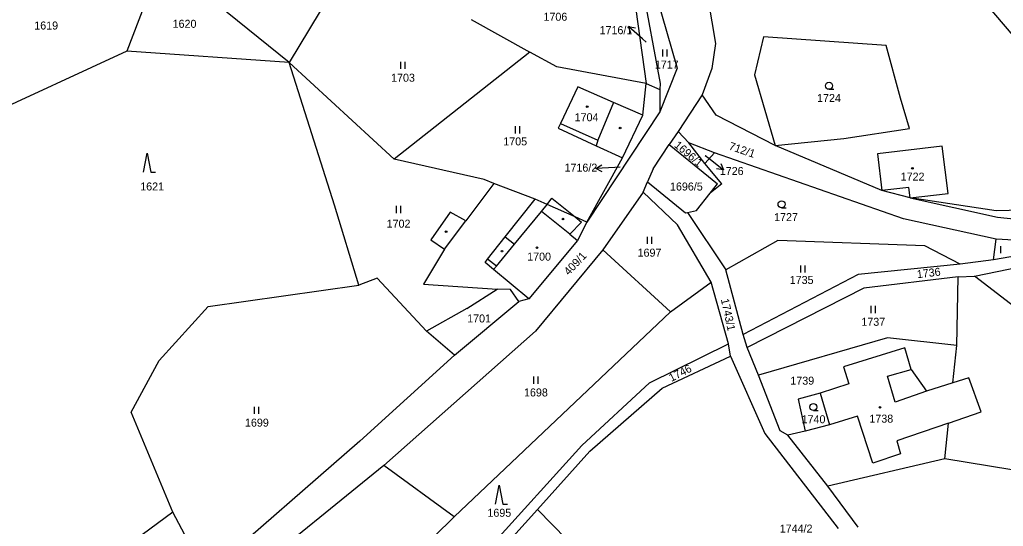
# Model space of a CAD drawing. Extents: x -670359 to -668019, y -978807 to -976674.
# Drawn here: x -669008.2 to -668799.4, y -978050.6 to -977943.1 of the extents above; entities that cross this region are included whole.
import ezdxf

# ---------------------------------------------------------------- set-up
doc = ezdxf.new("R2010")
doc.units = 0
for name, color, linetype in [('Hranice parcel', 7, 'Continuous'), ('Parcelní čísla', 7, 'Continuous'), ('Vnitřní kresba', 7, 'Continuous'), ('Značky budov', 7, 'Continuous'), ('Značky kultur', 7, 'Continuous')]:
    doc.layers.add(name, color=color, linetype=linetype)

msp = doc.modelspace()

# ---------------------------------------------------------------- linework, layer by layer
at = {"layer": 'Hranice parcel'}
for points in [[(-668950.95, -977952.16), (-668977.32, -977930.92)], [(-668980.01, -977935.45), (-668985.45, -977949.79)], [(-668878.27, -977934.25), (-668875.21, -977956.62)], [(-668876.13, -977935.64), (-668872.25, -977956.67)], [(-668795.2, -977948.83), (-668806.66, -977935.37)], [(-668942.34, -977937.8), (-668950.95, -977952.16)], [(-668872.97, -977938.1), (-668868.6, -977953.38)], [(-668862.02, -977938.85), (-668860.5, -977948.16)], [(-668912.34, -977943.09), (-668899.89, -977950)], [(-668860.5, -977948.16), (-668861.23, -977953.43)], [(-668850.31, -977946.74), (-668852.21, -977954.78)], [(-668824.25, -977948.56), (-668850.31, -977946.74)], [(-668985.45, -977949.79), (-669016.41, -977964.09)], [(-668950.95, -977952.16), (-668985.45, -977949.79)], [(-668899.89, -977950), (-668928.72, -977972.71)], [(-668894.15, -977953.08), (-668899.89, -977950)], [(-668821.16, -977959.73), (-668824.25, -977948.56)], [(-668928.72, -977972.71), (-668950.95, -977952.16)], [(-668941.36, -977982.5), (-668950.95, -977952.16)], [(-668875.21, -977956.62), (-668894.15, -977953.08)], [(-668868.6, -977953.38), (-668872.28, -977962.67)], [(-668861.23, -977953.43), (-668863.33, -977959.07)], [(-668875.89, -977963.33), (-668875.21, -977956.62)], [(-668875.21, -977956.62), (-668872.26, -977957.9)], [(-668872.25, -977956.67), (-668872.26, -977957.9)], [(-668852.21, -977954.78), (-668847.83, -977969.82)], [(-668889.71, -977957.32), (-668893.37, -977965.1)], [(-668882.09, -977960.66), (-668889.71, -977957.32)], [(-668872.26, -977957.9), (-668872.28, -977962.67)], [(-668875.89, -977963.33), (-668882.09, -977960.66)], [(-668863.33, -977959.07), (-668868.43, -977966.82)], [(-668860.36, -977963.36), (-668863.33, -977959.07)], [(-668819.27, -977966.16), (-668821.16, -977959.73)], [(-668872.28, -977962.67), (-668887.81, -977986.07)], [(-668880.21, -977972.45), (-668875.89, -977963.33)], [(-668847.83, -977969.82), (-668860.36, -977963.36)], [(-668893.37, -977965.1), (-668893.85, -977966.12)], [(-668893.85, -977966.12), (-668885.77, -977969.87)], [(-668868.43, -977966.82), (-668870.29, -977969.61)], [(-668866.15, -977969.26), (-668868.43, -977966.82)], [(-668833.24, -977968.32), (-668819.27, -977966.16)], [(-668847.83, -977969.82), (-668833.24, -977968.32)], [(-668885.77, -977969.87), (-668880.21, -977972.45)], [(-668873.69, -977974.72), (-668870.29, -977969.61)], [(-668870.29, -977969.61), (-668860.04, -977977.91)], [(-668860.66, -977971.35), (-668866.15, -977969.26)], [(-668862.7, -977973.64), (-668866.15, -977969.26)], [(-668825.18, -977979.34), (-668847.83, -977969.82)], [(-668812.37, -977969.97), (-668826.09, -977971.56)], [(-668811.11, -977979.99), (-668812.37, -977969.97)], [(-668909.59, -977977.05), (-668928.72, -977972.71)], [(-668887.81, -977986.07), (-668880.21, -977972.45)], [(-668862.7, -977973.64), (-668860.66, -977971.35)], [(-668820.56, -977985.34), (-668860.66, -977971.35)], [(-668826.09, -977971.56), (-668825.18, -977979.34)], [(-668873.69, -977974.72), (-668874.91, -977977.53)], [(-668859.09, -977977.94), (-668862.7, -977973.64)], [(-668907.52, -977977.89), (-668909.59, -977977.05)], [(-668875.85, -977979.73), (-668874.91, -977977.53)], [(-668874.91, -977977.53), (-668866.83, -977984.08)], [(-668907.52, -977977.89), (-668913.5, -977985.78)], [(-668898.77, -977981.16), (-668907.52, -977977.89)], [(-668861.63, -977979.94), (-668860.04, -977977.91)], [(-668859.09, -977977.94), (-668861.63, -977979.94)], [(-668819.13, -977980.89), (-668825.18, -977979.34)], [(-668896.23, -977982.3), (-668898.77, -977981.16)], [(-668875.85, -977979.73), (-668884.39, -977991.97)], [(-668868.53, -977986.65), (-668875.85, -977979.73)], [(-668864.53, -977983.62), (-668861.63, -977979.94)], [(-668819.13, -977980.89), (-668811.11, -977979.99)], [(-668800.92, -977983.69), (-668819.13, -977980.89)], [(-668819.13, -977980.89), (-668800.6, -977985.03)], [(-668936.18, -977999.43), (-668941.36, -977982.5)], [(-668890.29, -977984.96), (-668896.23, -977982.3)], [(-668866.43, -977984), (-668864.53, -977983.62)], [(-668778.82, -977983.12), (-668800.92, -977983.69)], [(-668916.83, -977983.96), (-668920.93, -977989.81)], [(-668913.5, -977985.78), (-668916.83, -977983.96)], [(-668887.81, -977986.07), (-668890.29, -977984.96)], [(-668866.83, -977984.08), (-668866.43, -977984)], [(-668866.43, -977984), (-668858.29, -977996.19)], [(-668800.87, -977989.69), (-668820.56, -977985.34)], [(-668800.6, -977985.03), (-668785.48, -977986.54)], [(-668887.81, -977986.07), (-668889.8, -977989.96)], [(-668861.38, -977998.78), (-668868.53, -977986.65)], [(-668920.93, -977989.81), (-668918, -977991.78)], [(-668889.8, -977989.96), (-668900.1, -978002.34)], [(-668847.22, -977989.99), (-668858.29, -977996.19)], [(-668816.02, -977991.1), (-668847.22, -977989.99)], [(-668801.42, -977994.08), (-668800.87, -977989.69)], [(-668782.24, -977990.74), (-668800.87, -977989.69)], [(-668918, -977991.78), (-668922.45, -977999.22)], [(-668884.39, -977991.97), (-668898.7, -978009.24)], [(-668870.05, -978005.11), (-668884.39, -977991.97)], [(-668808.56, -977994.99), (-668816.02, -977991.1)], [(-668782.24, -977990.74), (-668801.42, -977994.08)], [(-668801.42, -977994.08), (-668808.56, -977994.99)], [(-668805.49, -977997.52), (-668781.08, -977992.49)], [(-668854.61, -978009.94), (-668858.29, -977996.19)], [(-668808.56, -977994.99), (-668830.21, -977997.17)], [(-668932.28, -977997.93), (-668936.18, -977999.43)], [(-668921.83, -978009.23), (-668932.28, -977997.93)], [(-668830.21, -977997.17), (-668854.61, -978009.94)], [(-668808.93, -977997.7), (-668828.98, -978000.07)], [(-668809.26, -978012.26), (-668808.93, -977997.7)], [(-668808.93, -977997.7), (-668805.49, -977997.52)], [(-668796.01, -978004.81), (-668805.49, -977997.52)], [(-668968.17, -978003.97), (-668936.18, -977999.43)], [(-668922.45, -977999.22), (-668906.79, -978000.3)], [(-668913.26, -978004.42), (-668906.79, -978000.3)], [(-668903.98, -978000.35), (-668906.79, -978000.3)], [(-668902.19, -978002.94), (-668903.98, -978000.35)], [(-668870.05, -978005.11), (-668861.38, -977998.78)], [(-668857.68, -978011.88), (-668861.38, -977998.78)], [(-668828.98, -978000.07), (-668853.77, -978012.67)], [(-668900.1, -978002.34), (-668902.19, -978002.94)], [(-668978.61, -978015.45), (-668968.17, -978003.97)], [(-668913.26, -978004.42), (-668921.83, -978009.23)], [(-668915.91, -978014.3), (-668902.19, -978002.94)], [(-668915.95, -978048.61), (-668870.05, -978005.11)], [(-668898.7, -978009.24), (-668930.88, -978037.71)], [(-668915.91, -978014.3), (-668921.83, -978009.23)], [(-668853.77, -978012.67), (-668854.61, -978009.94)], [(-668823.96, -978010.64), (-668851.31, -978018.56)], [(-668809.26, -978012.26), (-668823.96, -978010.64)], [(-668874.47, -978020.15), (-668857.68, -978011.88)], [(-668857.25, -978014.53), (-668857.68, -978011.88)], [(-668851.31, -978018.56), (-668853.77, -978012.67)], [(-668820.24, -978012.78), (-668833.27, -978016.79)], [(-668818.96, -978017.37), (-668820.24, -978012.78)], [(-668810.09, -978020.2), (-668809.26, -978012.26)], [(-668915.91, -978014.3), (-668936, -978032.58)], [(-668871.77, -978021.31), (-668857.25, -978014.53)], [(-668857.25, -978014.53), (-668850.01, -978030.9)], [(-668984.49, -978026.43), (-668978.61, -978015.45)], [(-668833.27, -978016.79), (-668832.14, -978020.41)], [(-668846.72, -978030.4), (-668851.31, -978018.56)], [(-668823.94, -978018.8), (-668818.96, -978017.37)], [(-668822.36, -978024.27), (-668823.94, -978018.8)], [(-668806.66, -978019.1), (-668810.09, -978020.2)], [(-668804.06, -978026.35), (-668806.66, -978019.1)], [(-668888.87, -978033.49), (-668874.47, -978020.15)], [(-668887.13, -978034.72), (-668871.77, -978021.31)], [(-668832.14, -978020.41), (-668838.25, -978022.39)], [(-668810.09, -978020.2), (-668815.67, -978021.98)], [(-668838.25, -978022.39), (-668842.92, -978023.66)], [(-668838.25, -978022.39), (-668836.29, -978029.06)], [(-668815.67, -978021.98), (-668822.36, -978024.27)], [(-668842.92, -978023.66), (-668841.43, -978030.41)], [(-668975.67, -978047.64), (-668984.49, -978026.43)], [(-668810.97, -978028.73), (-668804.06, -978026.35)], [(-668836.29, -978029.06), (-668841.43, -978030.41)], [(-668811.76, -978036.29), (-668810.97, -978028.73)], [(-668850.01, -978030.9), (-668834.43, -978051.09)], [(-668845.13, -978031.3), (-668846.72, -978030.4)], [(-668841.43, -978030.41), (-668845.13, -978031.3)], [(-668836.59, -978042.09), (-668845.13, -978031.3)], [(-668936, -978032.58), (-668968.61, -978060.99)], [(-668908.45, -978055.15), (-668888.87, -978033.49)], [(-668887.13, -978034.72), (-668898.28, -978047.1)], [(-668930.88, -978037.71), (-668960.68, -978061.9)], [(-668915.95, -978048.61), (-668930.88, -978037.71)], [(-668811.76, -978036.29), (-668836.59, -978042.09)], [(-668779.04, -978041.67), (-668811.76, -978036.29)], [(-668830.18, -978050.85), (-668836.59, -978042.09)], [(-668975.67, -978047.64), (-668982.21, -978052.45)], [(-668968.61, -978060.99), (-668975.67, -978047.64)], [(-668906.72, -978056.46), (-668898.28, -978047.1)], [(-668882.71, -978063.01), (-668898.28, -978047.1)], [(-668953.8, -978085.85), (-668915.95, -978048.61)]]:
    msp.add_lwpolyline(points, dxfattribs=at)
at = {"layer": 'Parcelní čísla'}
for p, q in [((-668878.45, -977945.94), (-668878.92, -977944.51)), ((-668875.2, -977947.84), (-668875.94, -977947.18)), ((-668862.64, -977971.89), (-668861.9, -977972.49)), ((-668884.52, -977975.38), (-668885.86, -977974.71)), ((-668880.68, -977974.38), (-668881.87, -977974.46)), ((-668859.33, -977973.6), (-668858.78, -977975))]:
    msp.add_line(p, q, dxfattribs=at)
for points in [[(-668875.94, -977947.18), (-668878.92, -977944.51), (-668877.45, -977944.82)], [(-668861.9, -977972.49), (-668858.78, -977975), (-668860.27, -977974.77)], [(-668881.87, -977974.46), (-668885.86, -977974.71), (-668884.61, -977973.88)]]:
    msp.add_lwpolyline(points, dxfattribs=at)
at = {"layer": 'Vnitřní kresba'}
for points in [[(-668882.09, -977960.66), (-668885.43, -977968.68)], [(-668893.37, -977965.1), (-668885.43, -977968.68)], [(-668885.43, -977968.68), (-668885.77, -977969.87)], [(-668819.41, -977978.72), (-668825.18, -977979.34)], [(-668819.13, -977980.89), (-668819.41, -977978.72)], [(-668905.15, -977989.21), (-668898.77, -977981.16)], [(-668896.23, -977982.3), (-668895.25, -977980.98)], [(-668895.25, -977980.98), (-668890.29, -977984.96)], [(-668903.15, -977990.77), (-668897.38, -977983.83)], [(-668897.38, -977983.83), (-668896.23, -977982.3)], [(-668891.38, -977988.65), (-668897.38, -977983.83)], [(-668918, -977991.78), (-668913.5, -977985.78)], [(-668890.29, -977984.96), (-668888.93, -977986.05)], [(-668888.93, -977986.05), (-668891.38, -977988.65)], [(-668908.84, -977993.94), (-668905.15, -977989.21)], [(-668905.15, -977989.21), (-668903.15, -977990.77)], [(-668891.38, -977988.65), (-668889.8, -977989.96)], [(-668906.98, -977995.39), (-668903.15, -977990.77)], [(-668909.38, -977994.64), (-668908.84, -977993.94)], [(-668906.98, -977995.39), (-668908.84, -977993.94)], [(-668907.59, -977996.12), (-668909.38, -977994.64)], [(-668907.59, -977996.12), (-668906.98, -977995.39)], [(-668900.1, -978002.34), (-668907.59, -977996.12)], [(-668818.96, -978017.37), (-668815.67, -978021.98)], [(-668830.33, -978027.24), (-668836.29, -978029.06)], [(-668827.06, -978037.22), (-668830.33, -978027.24)], [(-668810.97, -978028.73), (-668821.94, -978032.51)], [(-668821.94, -978032.51), (-668821.19, -978035.25)], [(-668821.19, -978035.25), (-668827.06, -978037.22)]]:
    msp.add_lwpolyline(points, dxfattribs=at)
at = {"layer": 'Značky budov'}
for centre in [(-668887.7, -977961.57), (-668818.66, -977974.66), (-668898.38, -977991.49), (-668825.54, -978025.39)]:
    msp.add_circle(centre, 0.175, dxfattribs=at)
at = {"layer": 'Značky kultur'}
for p, q in [((-668871.7, -977949.41), (-668871.7, -977950.91)), ((-668870.7, -977950.91), (-668870.7, -977949.41)), ((-668927.34, -977952.06), (-668927.34, -977953.56)), ((-668926.34, -977953.56), (-668926.34, -977952.06)), ((-668836.37, -977957.87), (-668835.37, -977957.87)), ((-668903.03, -977965.73), (-668903.03, -977967.23)), ((-668902.03, -977967.23), (-668902.03, -977965.73)), ((-668928.28, -977982.64), (-668928.28, -977984.14)), ((-668927.28, -977984.14), (-668927.28, -977982.64)), ((-668846.45, -977983.03), (-668845.45, -977983.03)), ((-668875.01, -977989.2), (-668875.01, -977990.7)), ((-668874.01, -977990.7), (-668874.01, -977989.2)), ((-668799.93, -977991.14), (-668799.93, -977992.64)), ((-668842.43, -977995.27), (-668842.43, -977996.77)), ((-668841.43, -977996.77), (-668841.43, -977995.27)), ((-668827.5, -978003.87), (-668827.5, -978005.37)), ((-668826.5, -978005.37), (-668826.5, -978003.87)), ((-668899.12, -978018.87), (-668899.12, -978020.37)), ((-668898.12, -978020.37), (-668898.12, -978018.87)), ((-668958.4, -978025.28), (-668958.4, -978026.78)), ((-668957.4, -978026.78), (-668957.4, -978025.28)), ((-668839.69, -978026.06), (-668838.69, -978026.06))]:
    msp.add_line(p, q, dxfattribs=at)
for points in [[(-668981.88, -977975.45), (-668981.13, -977971.45), (-668980.38, -977975.45), (-668979.38, -977975.45)], [(-668907.14, -978045.91), (-668906.39, -978041.91), (-668905.64, -978045.91), (-668904.64, -978045.91)]]:
    msp.add_lwpolyline(points, dxfattribs=at)
for centre, radius in [((-668836.37, -977957.12), 0.75), ((-668887.7, -977961.57), 0.175), ((-668880.72, -977966.1), 0.175), ((-668818.66, -977974.66), 0.175), ((-668846.45, -977982.28), 0.75), ((-668892.86, -977985.42), 0.175), ((-668917.65, -977988.09), 0.175), ((-668905.78, -977992.23), 0.175), ((-668898.38, -977991.49), 0.175), ((-668839.69, -978025.31), 0.75), ((-668825.54, -978025.39), 0.175)]:
    msp.add_circle(centre, radius, dxfattribs=at)

# ---------------------------------------------------------------- texts
at = {"layer": 'Parcelní čísla'}
for s, height, p in [('1706', 1.7, (-668896.99, -977943.32)), ('1619', 1.7, (-669005.09, -977945.18)), ('1620', 1.7, (-668975.72, -977944.82)), ('1716/1', 1.7, (-668885.08, -977946.17)), ('1716/1', 0.1, (-668875.41, -977947.84)), ('1717', 1.7, (-668873.34, -977953.46)), ('1703', 1.7, (-668929.34, -977956.26)), ('1724', 1.7, (-668838.91, -977960.57)), ('1704', 1.7, (-668890.37, -977964.65)), ('1705', 1.7, (-668905.52, -977969.78)), ('1726', 0.1, (-668862.64, -977971.89)), ('1716/2', 1.7, (-668892.52, -977975.35)), ('1716/2', 0.1, (-668880.91, -977974.38)), ('1726', 1.7, (-668859.56, -977976.07)), ('1696/5', 1.7, (-668870.13, -977979.36)), ('1722', 1.7, (-668821.16, -977977.26)), ('1621', 1.7, (-668982.6, -977979.35)), ('1702', 1.7, (-668930.28, -977987.25)), ('1727', 1.7, (-668848.03, -977985.86)), ('1697', 1.7, (-668877.01, -977993.4)), ('1700', 1.7, (-668900.45, -977994.24)), ('1735', 1.7, (-668844.71, -977999.19)), ('1701', 1.7, (-668913.19, -978007.36)), ('1737', 1.7, (-668829.5, -978008.07)), ('1739', 1.7, (-668844.58, -978020.57)), ('1698', 1.7, (-668901.12, -978023.07)), ('1740', 1.7, (-668842.19, -978028.76)), ('1738', 1.7, (-668827.8, -978028.63)), ('1699', 1.7, (-668960.36, -978029.48)), ('1695', 1.7, (-668908.89, -978048.61)), ('1744/2', 1.7, (-668846.83, -978051.97))]:
    msp.add_text(s, height=height, dxfattribs=at).set_placement(p)
for s, rotation, p in [('1696/1', 319.8029, (-668869.38, -977969.96)), ('712/1', 341.1588, (-668857.77, -977970.61)), ('409/1', 46.6366, (-668891.61, -977997.49)), ('1736', 6.6624, (-668817.63, -977997.98)), ('1743/1', 282.3349, (-668859.34, -978002.48)), ('1746', 27.21, (-668869.84, -978020))]:
    msp.add_text(s, height=1.7, rotation=rotation, dxfattribs=at).set_placement(p)

doc.saveas('drawing.dxf')
